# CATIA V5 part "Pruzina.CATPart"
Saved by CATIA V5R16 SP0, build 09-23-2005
Part number: Pruzina
Bounding box of the stored display mesh (mm): x -22.5 to 22.5, y -22.5 to 22.5, z 0 to 100
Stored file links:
  H:\Dokumenty\CATIA\diskuze_catia\pruzina\Pruzina.CATPart
  H:\Dokumenty\CATIA\diskuze_catia\pruzina\Product1.CATProduct
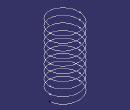
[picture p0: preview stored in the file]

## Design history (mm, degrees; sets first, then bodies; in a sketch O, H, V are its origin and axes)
Parameters
  vyska = 100 mm {= External.vyska_sestava}
External parameters (linked from other documents)
  External.vyska_sestava = 100 mm
Body1 (main body)
  Sketch1 on xy-plane, origin (0, 0, 0), H (1, 0, 0), V (0, 1, 0)
    point P1 (22.5, 0)
    distance P1 V = 22.5
    coincidence: P1 H
  Helix1: Direction Z axis, RefPoint Sketch1, Pitch 10 {= Helix1.Height /10}, Height 100 {= vyska}, TaperAngle 0
  Sketch2 on zx-plane, origin (0, 0, 0), H (-1, 0, 0), V (0, 0, 1)
    circle A1 centre (-22.5, 0) radius 2.5
    point P1 (-22.5, 0)
    reference projected point E1 (-22.5, 0) from Sketch1
    radius A1 = 2.5
    coincidence: P1 H, P1 E1
  Set1
    Sweep1: type Unspec, Profile Sketch2, Guide Helix1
